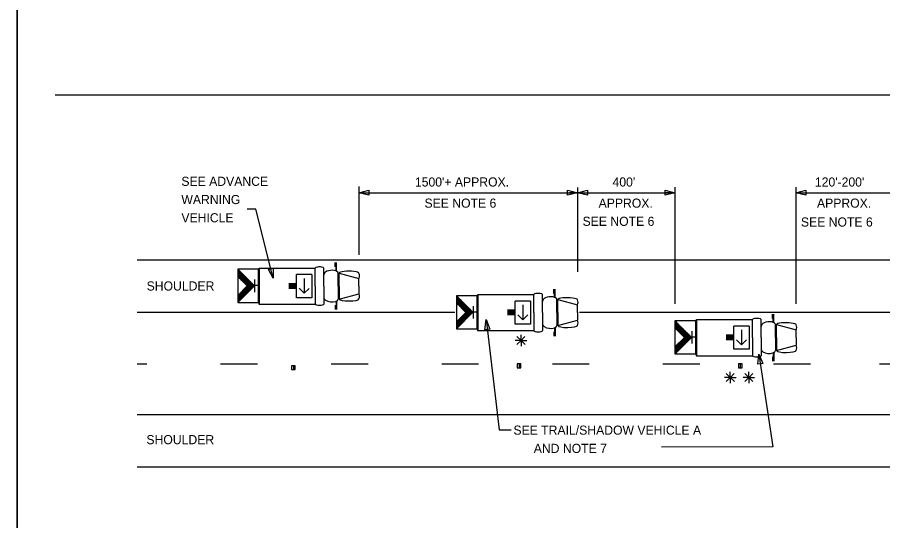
# Model space of a CAD drawing. Extents: x 1374027 to 1374537, y 380415 to 381405.
# Drawn here: x 1374027.1 to 1374084, y 381338.9 to 381372.1 of the extents above; entities that cross this region are included whole.
import ezdxf

# ---------------------------------------------------------------- set-up
doc = ezdxf.new("R2010")
doc.units = 0
for name, color, linetype in [('DSN_DRFT_Junk-No-Plot', 7, 'Continuous'), ('Level 1', 7, 'Continuous'), ('Working Level 1', 7, 'Continuous')]:
    doc.layers.add(name, color=color, linetype=linetype)

msp = doc.modelspace()

# ---------------------------------------------------------------- linework, layer by layer
at = {"layer": 'DSN_DRFT_Junk-No-Plot'}
for points in [[(1374027.083, 381405.174), (1374197.083, 381405.174), (1374197.083, 381295.174), (1374027.083, 381295.174)], [(1374027.083, 381405.174), (1374027.083, 381295.174), (1374197.083, 381295.174), (1374197.083, 381405.174)]]:
    msp.add_lwpolyline(points, close=True, dxfattribs=at)
at = {"layer": 'Level 1'}
msp.add_lwpolyline([(1374075.872, 381349.898), (1374076.792, 381343.794), (1374069.464, 381343.766)], dxfattribs=at)
at = {"layer": 'Working Level 1'}
for p, q in [((1374029.583, 381366.948), (1374114.982, 381366.948)), ((1374049.557, 381360.921), (1374049.557, 381356.423)), ((1374063.944, 381360.862), (1374063.944, 381355.317)), ((1374070.358, 381360.886), (1374070.358, 381353.197)), ((1374078.312, 381360.886), (1374078.312, 381353.197)), ((1374049.557, 381360.515), (1374050.113, 381360.515)), ((1374049.557, 381360.515), (1374063.944, 381360.515)), ((1374063.944, 381360.515), (1374063.415, 381360.515)), ((1374063.944, 381360.515), (1374064.562, 381360.515)), ((1374063.944, 381360.515), (1374070.358, 381360.515)), ((1374070.285, 381360.515), (1374069.756, 381360.515)), ((1374078.312, 381360.515), (1374078.93, 381360.515)), ((1374078.312, 381360.515), (1374084.726, 381360.515)), ((1374034.976, 381356.094), (1374114.982, 381356.094)), ((1374048.007, 381355.628), (1374048.007, 381355.919)), ((1374048.054, 381355.349), (1374048.054, 381355.919)), ((1374048.093, 381355.349), (1374048.093, 381355.919)), ((1374041.585, 381355.48), (1374042.68, 381354.385)), ((1374042.995, 381355.53), (1374042.995, 381353.153)), ((1374043.005, 381355.558), (1374043.005, 381353.181)), ((1374043.005, 381353.18), (1374043.005, 381355.557)), ((1374043.005, 381355.557), (1374046.684, 381355.557)), ((1374046.468, 381355.13), (1374045.462, 381355.13)), ((1374045.462, 381353.608), (1374045.462, 381355.13)), ((1374046.468, 381355.13), (1374046.468, 381353.608)), ((1374046.684, 381354.369), (1374046.684, 381355.557)), ((1374047.248, 381354.369), (1374047.248, 381355.557)), ((1374048.192, 381354.369), (1374048.192, 381355.225)), ((1374048.271, 381355.225), (1374049.557, 381354.873)), ((1374048.271, 381354.369), (1374048.271, 381355.225)), ((1374041.585, 381355.005), (1374042.213, 381354.378)), ((1374042.717, 381353.973), (1374042.717, 381354.797)), ((1374045.462, 381354.521), (1374044.95, 381354.521)), ((1374045.965, 381354.871), (1374045.965, 381353.898)), ((1374049.557, 381354.369), (1374049.557, 381354.873)), ((1374041.585, 381353.752), (1374042.213, 381354.378)), ((1374041.59, 381353.295), (1374042.68, 381354.385)), ((1374042.946, 381354.405), (1374042.711, 381354.405)), ((1374045.462, 381354.445), (1374044.95, 381354.445)), ((1374045.462, 381354.369), (1374044.95, 381354.369)), ((1374045.462, 381354.293), (1374044.95, 381354.293)), ((1374045.462, 381354.217), (1374044.95, 381354.217)), ((1374045.965, 381353.898), (1374045.634, 381354.229)), ((1374045.965, 381353.898), (1374046.288, 381354.221)), ((1374046.684, 381354.369), (1374046.684, 381353.181)), ((1374047.248, 381354.369), (1374047.248, 381353.181)), ((1374048.192, 381354.369), (1374048.192, 381353.513)), ((1374048.271, 381354.369), (1374048.271, 381353.513)), ((1374049.557, 381354.369), (1374049.557, 381353.865)), ((1374062.394, 381353.887), (1374062.394, 381354.178)), ((1374062.44, 381353.607), (1374062.44, 381354.178)), ((1374062.479, 381353.607), (1374062.479, 381354.178)), ((1374046.468, 381353.608), (1374045.462, 381353.608)), ((1374048.054, 381353.39), (1374048.054, 381352.819)), ((1374048.093, 381353.39), (1374048.093, 381352.819)), ((1374048.271, 381353.513), (1374049.557, 381353.865)), ((1374055.971, 381353.739), (1374057.067, 381352.644)), ((1374057.382, 381353.789), (1374057.382, 381351.412)), ((1374057.391, 381353.817), (1374057.391, 381351.44)), ((1374057.391, 381351.439), (1374057.391, 381353.816)), ((1374057.391, 381353.816), (1374061.071, 381353.816)), ((1374060.854, 381353.388), (1374059.849, 381353.388)), ((1374059.849, 381351.867), (1374059.849, 381353.388)), ((1374060.854, 381353.388), (1374060.854, 381351.867)), ((1374061.071, 381352.628), (1374061.071, 381353.816)), ((1374061.634, 381352.628), (1374061.634, 381353.816)), ((1374062.579, 381352.628), (1374062.579, 381353.484)), ((1374062.657, 381353.484), (1374063.943, 381353.132)), ((1374062.657, 381352.628), (1374062.657, 381353.484)), ((1374043.005, 381353.181), (1374046.684, 381353.181)), ((1374048.007, 381353.109), (1374048.007, 381352.819)), ((1374055.971, 381353.263), (1374056.599, 381352.637)), ((1374057.104, 381352.232), (1374057.104, 381353.056)), ((1374059.849, 381352.779), (1374059.336, 381352.779)), ((1374060.352, 381353.13), (1374060.352, 381352.157)), ((1374063.943, 381352.628), (1374063.943, 381353.132)), ((1374034.976, 381352.646), (1374049.603, 381352.646)), ((1374049.581, 381352.646), (1374055.876, 381352.646)), ((1374055.971, 381352.011), (1374056.599, 381352.637)), ((1374055.977, 381351.554), (1374057.067, 381352.644)), ((1374057.333, 381352.664), (1374057.097, 381352.664)), ((1374059.849, 381352.703), (1374059.336, 381352.703)), ((1374059.849, 381352.627), (1374059.336, 381352.627)), ((1374059.849, 381352.551), (1374059.336, 381352.551)), ((1374059.849, 381352.475), (1374059.336, 381352.475)), ((1374060.352, 381352.157), (1374060.021, 381352.488)), ((1374060.352, 381352.157), (1374060.675, 381352.48)), ((1374061.071, 381352.628), (1374061.071, 381351.44)), ((1374061.634, 381352.628), (1374061.634, 381351.44)), ((1374062.579, 381352.628), (1374062.579, 381351.772)), ((1374062.657, 381352.628), (1374062.657, 381351.772)), ((1374063.943, 381352.628), (1374063.943, 381352.124)), ((1374064.074, 381352.646), (1374114.982, 381352.646)), ((1374076.781, 381352.239), (1374076.781, 381352.53)), ((1374076.827, 381351.96), (1374076.827, 381352.53)), ((1374076.866, 381351.96), (1374076.866, 381352.53)), ((1374060.854, 381351.867), (1374059.849, 381351.867)), ((1374062.44, 381351.648), (1374062.44, 381351.078)), ((1374062.479, 381351.648), (1374062.479, 381351.078)), ((1374062.657, 381351.772), (1374063.943, 381352.124)), ((1374070.358, 381352.091), (1374071.453, 381350.996)), ((1374070.358, 381351.616), (1374070.986, 381350.989)), ((1374071.768, 381352.141), (1374071.768, 381349.764)), ((1374071.778, 381352.169), (1374071.778, 381349.792)), ((1374071.778, 381349.791), (1374071.778, 381352.168)), ((1374071.778, 381352.168), (1374075.457, 381352.168)), ((1374075.241, 381351.741), (1374074.236, 381351.741)), ((1374074.236, 381350.219), (1374074.236, 381351.741)), ((1374075.241, 381351.741), (1374075.241, 381350.219)), ((1374075.457, 381350.98), (1374075.457, 381352.168)), ((1374076.021, 381350.98), (1374076.021, 381352.168)), ((1374076.965, 381350.98), (1374076.965, 381351.836)), ((1374077.044, 381351.836), (1374078.33, 381351.484)), ((1374077.044, 381350.98), (1374077.044, 381351.836)), ((1374057.391, 381351.44), (1374061.071, 381351.44)), ((1374060.227, 381350.784), (1374059.961, 381351.05)), ((1374060.22, 381350.779), (1374060.487, 381351.045)), ((1374060.227, 381350.784), (1374060.227, 381351.161)), ((1374062.394, 381351.368), (1374062.394, 381351.078)), ((1374071.49, 381350.584), (1374071.49, 381351.408)), ((1374074.236, 381351.131), (1374073.723, 381351.131)), ((1374074.236, 381351.056), (1374073.723, 381351.056)), ((1374074.738, 381351.482), (1374074.738, 381350.509)), ((1374078.33, 381350.98), (1374078.33, 381351.484)), ((1374060.227, 381350.784), (1374059.85, 381350.784)), ((1374060.227, 381350.784), (1374059.961, 381350.518)), ((1374060.227, 381350.784), (1374060.493, 381350.518)), ((1374060.227, 381350.784), (1374060.227, 381350.408)), ((1374060.227, 381350.784), (1374060.603, 381350.784)), ((1374070.358, 381350.363), (1374070.986, 381350.989)), ((1374070.364, 381349.906), (1374071.453, 381350.996)), ((1374071.719, 381351.016), (1374071.484, 381351.016)), ((1374074.236, 381350.98), (1374073.723, 381350.98)), ((1374074.236, 381350.904), (1374073.723, 381350.904)), ((1374074.236, 381350.828), (1374073.723, 381350.828)), ((1374074.738, 381350.509), (1374074.408, 381350.84)), ((1374074.738, 381350.509), (1374075.061, 381350.832)), ((1374075.457, 381350.98), (1374075.457, 381349.792)), ((1374076.021, 381350.98), (1374076.021, 381349.792)), ((1374076.965, 381350.98), (1374076.965, 381350.124)), ((1374077.044, 381350.98), (1374077.044, 381350.124)), ((1374077.044, 381350.124), (1374078.33, 381350.476)), ((1374078.33, 381350.98), (1374078.33, 381350.476)), ((1374075.241, 381350.219), (1374074.236, 381350.219)), ((1374076.827, 381350.001), (1374076.827, 381349.43)), ((1374076.866, 381350.001), (1374076.866, 381349.43)), ((1374071.778, 381349.792), (1374075.457, 381349.792)), ((1374076.781, 381349.72), (1374076.781, 381349.43)), ((1374045.371, 381349.123), (1374045.128, 381349.123)), ((1374045.128, 381349.123), (1374045.128, 381348.88)), ((1374045.128, 381348.88), (1374045.371, 381348.88)), ((1374045.25, 381349.123), (1374045.249, 381348.88)), ((1374045.371, 381348.88), (1374045.371, 381349.123)), ((1374060.225, 381349.244), (1374059.982, 381349.244)), ((1374059.982, 381349.244), (1374059.982, 381349.001)), ((1374059.982, 381349.001), (1374060.225, 381349.001)), ((1374060.104, 381349.244), (1374060.104, 381349.001)), ((1374060.225, 381349.001), (1374060.225, 381349.244)), ((1374074.53, 381349.244), (1374074.529, 381349.001)), ((1374074.529, 381349.001), (1374074.772, 381349.001)), ((1374074.772, 381349.244), (1374074.53, 381349.244)), ((1374074.652, 381349.244), (1374074.651, 381349.001)), ((1374074.772, 381349.001), (1374074.772, 381349.244)), ((1374073.999, 381348.349), (1374073.622, 381348.349)), ((1374073.999, 381348.349), (1374073.733, 381348.615)), ((1374073.999, 381348.349), (1374073.733, 381348.083)), ((1374073.992, 381348.344), (1374074.259, 381348.61)), ((1374073.999, 381348.349), (1374073.999, 381348.725)), ((1374073.999, 381348.349), (1374074.265, 381348.083)), ((1374073.999, 381348.349), (1374073.999, 381347.973)), ((1374073.999, 381348.349), (1374074.375, 381348.349)), ((1374075.216, 381348.349), (1374074.839, 381348.349)), ((1374075.216, 381348.349), (1374074.95, 381348.615)), ((1374075.216, 381348.349), (1374074.95, 381348.083)), ((1374075.209, 381348.344), (1374075.476, 381348.61)), ((1374075.216, 381348.349), (1374075.216, 381348.725)), ((1374075.216, 381348.349), (1374075.482, 381348.083)), ((1374075.216, 381348.349), (1374075.216, 381347.973)), ((1374075.216, 381348.349), (1374075.592, 381348.349)), ((1374034.976, 381345.924), (1374099.811, 381345.924)), ((1374034.976, 381342.476), (1374096.124, 381342.476))]:
    msp.add_line(p, q, dxfattribs=at)
for points in [[(1374050.206, 381360.353), (1374049.556, 381360.515), (1374050.206, 381360.678)], [(1374063.294, 381360.678), (1374063.944, 381360.515), (1374063.294, 381360.353)], [(1374064.594, 381360.353), (1374063.944, 381360.515), (1374064.594, 381360.678)], [(1374069.708, 381360.678), (1374070.358, 381360.515), (1374069.708, 381360.353)], [(1374078.962, 381360.353), (1374078.312, 381360.515), (1374078.962, 381360.678)], [(1374041.585, 381355.48), (1374041.585, 381353.295), (1374042.95, 381353.295), (1374042.95, 381355.48)], [(1374043.924, 381355.552), (1374043.927, 381354.882), (1374043.609, 381355.472)], [(1374055.971, 381353.739), (1374055.971, 381351.553), (1374057.337, 381351.553), (1374057.337, 381353.739)], [(1374057.847, 381351.498), (1374057.931, 381352.162), (1374058.169, 381351.536)], [(1374070.358, 381352.091), (1374070.358, 381349.906), (1374071.723, 381349.906), (1374071.723, 381352.091)], [(1374075.808, 381349.231), (1374075.872, 381349.898), (1374076.13, 381349.28)]]:
    msp.add_lwpolyline(points, close=True, dxfattribs=at)
for points in [[(1374043.927, 381354.882), (1374042.773, 381359.426), (1374042.197, 381359.426)], [(1374041.585, 381355.428), (1374042.163, 381354.427)], [(1374041.585, 381355.343), (1374042.048, 381354.539)], [(1374041.585, 381355.256), (1374041.934, 381354.651)], [(1374041.585, 381355.17), (1374041.819, 381354.764)], [(1374041.585, 381355.084), (1374041.705, 381354.876)], [(1374041.634, 381355.432), (1374042.398, 381354.105)], [(1374041.75, 381355.314), (1374042.43, 381354.136)], [(1374041.868, 381355.197), (1374042.462, 381354.168)], [(1374041.985, 381355.079), (1374042.494, 381354.199)], [(1374041.585, 381354.998), (1374041.59, 381354.988)], [(1374042.103, 381354.962), (1374042.525, 381354.231)], [(1374042.22, 381354.844), (1374042.558, 381354.26)], [(1374042.338, 381354.727), (1374042.59, 381354.29)], [(1374042.456, 381354.611), (1374042.619, 381354.326)], [(1374042.564, 381354.503), (1374042.648, 381354.357)], [(1374041.725, 381353.893), (1374041.893, 381353.602)], [(1374041.757, 381353.924), (1374041.925, 381353.633)], [(1374041.788, 381353.956), (1374041.956, 381353.664)], [(1374041.82, 381353.987), (1374041.988, 381353.696)], [(1374041.852, 381354.019), (1374042.02, 381353.727)], [(1374041.883, 381354.051), (1374042.052, 381353.759)], [(1374041.915, 381354.082), (1374042.083, 381353.79)], [(1374041.946, 381354.113), (1374042.114, 381353.822)], [(1374041.978, 381354.145), (1374042.147, 381353.853)], [(1374042.009, 381354.177), (1374042.177, 381353.885)], [(1374042.041, 381354.207), (1374042.209, 381353.916)], [(1374042.073, 381354.24), (1374042.241, 381353.948)], [(1374042.104, 381354.271), (1374042.273, 381353.98)], [(1374042.136, 381354.302), (1374042.304, 381354.01)], [(1374042.167, 381354.334), (1374042.336, 381354.042)], [(1374042.199, 381354.366), (1374042.368, 381354.074)], [(1374041.585, 381353.706), (1374041.735, 381353.444)], [(1374041.585, 381353.619), (1374041.704, 381353.413)], [(1374041.585, 381353.534), (1374041.672, 381353.382)], [(1374041.585, 381353.447), (1374041.641, 381353.35)], [(1374041.585, 381353.361), (1374041.609, 381353.32)], [(1374041.599, 381353.767), (1374041.767, 381353.477)], [(1374041.631, 381353.799), (1374041.799, 381353.507)], [(1374041.662, 381353.83), (1374041.83, 381353.539)], [(1374041.694, 381353.862), (1374041.862, 381353.57)], [(1374055.971, 381353.687), (1374056.549, 381352.686)], [(1374055.971, 381353.602), (1374056.435, 381352.798)], [(1374055.971, 381353.515), (1374056.321, 381352.91)], [(1374055.971, 381353.429), (1374056.206, 381353.023)], [(1374055.971, 381353.343), (1374056.092, 381353.135)], [(1374056.02, 381353.691), (1374056.785, 381352.364)], [(1374056.137, 381353.573), (1374056.817, 381352.395)], [(1374056.254, 381353.456), (1374056.849, 381352.427)], [(1374056.372, 381353.338), (1374056.88, 381352.458)], [(1374055.971, 381353.257), (1374055.977, 381353.247)], [(1374056.489, 381353.221), (1374056.911, 381352.49)], [(1374056.607, 381353.103), (1374056.944, 381352.519)], [(1374056.724, 381352.986), (1374056.977, 381352.549)], [(1374056.842, 381352.869), (1374057.006, 381352.585)], [(1374056.951, 381352.762), (1374057.035, 381352.616)], [(1374056.144, 381352.183), (1374056.311, 381351.892)], [(1374056.175, 381352.214), (1374056.343, 381351.923)], [(1374056.207, 381352.246), (1374056.375, 381351.955)], [(1374056.239, 381352.278), (1374056.406, 381351.986)], [(1374056.27, 381352.309), (1374056.438, 381352.018)], [(1374056.301, 381352.341), (1374056.469, 381352.049)], [(1374056.332, 381352.372), (1374056.501, 381352.081)], [(1374056.365, 381352.404), (1374056.533, 381352.111)], [(1374056.396, 381352.435), (1374056.564, 381352.144)], [(1374056.427, 381352.466), (1374056.596, 381352.175)], [(1374056.459, 381352.499), (1374056.628, 381352.206)], [(1374056.491, 381352.53), (1374056.659, 381352.238)], [(1374056.522, 381352.561), (1374056.69, 381352.269)], [(1374056.553, 381352.593), (1374056.723, 381352.301)], [(1374056.586, 381352.624), (1374056.754, 381352.332)], [(1374055.971, 381351.965), (1374056.122, 381351.703)], [(1374055.971, 381351.878), (1374056.09, 381351.672)], [(1374055.971, 381351.792), (1374056.059, 381351.641)], [(1374055.971, 381351.706), (1374056.028, 381351.609)], [(1374055.971, 381351.62), (1374055.995, 381351.578)], [(1374055.986, 381352.026), (1374056.153, 381351.736)], [(1374056.018, 381352.058), (1374056.185, 381351.766)], [(1374056.049, 381352.088), (1374056.216, 381351.798)], [(1374056.081, 381352.121), (1374056.248, 381351.829)], [(1374056.112, 381352.152), (1374056.28, 381351.861)], [(1374057.931, 381352.162), (1374058.794, 381344.903), (1374059.584, 381344.903)], [(1374070.358, 381352.039), (1374070.936, 381351.038)], [(1374070.358, 381351.954), (1374070.821, 381351.15)], [(1374070.358, 381351.867), (1374070.707, 381351.262)], [(1374070.358, 381351.781), (1374070.592, 381351.375)], [(1374070.358, 381351.695), (1374070.478, 381351.487)], [(1374070.358, 381351.609), (1374070.364, 381351.599)], [(1374070.407, 381352.043), (1374071.172, 381350.716)], [(1374070.523, 381351.925), (1374071.203, 381350.747)], [(1374070.641, 381351.808), (1374071.235, 381350.779)], [(1374070.759, 381351.69), (1374071.267, 381350.81)], [(1374070.876, 381351.573), (1374071.298, 381350.842)], [(1374070.993, 381351.455), (1374071.331, 381350.871)], [(1374071.111, 381351.338), (1374071.363, 381350.901)], [(1374071.229, 381351.222), (1374071.392, 381350.937)], [(1374071.337, 381351.114), (1374071.422, 381350.968)], [(1374070.467, 381350.473), (1374070.635, 381350.181)], [(1374070.498, 381350.504), (1374070.666, 381350.213)], [(1374070.53, 381350.535), (1374070.698, 381350.244)], [(1374070.562, 381350.567), (1374070.73, 381350.275)], [(1374070.593, 381350.598), (1374070.761, 381350.307)], [(1374070.625, 381350.63), (1374070.793, 381350.338)], [(1374070.657, 381350.662), (1374070.825, 381350.37)], [(1374070.688, 381350.693), (1374070.856, 381350.401)], [(1374070.719, 381350.724), (1374070.887, 381350.433)], [(1374070.751, 381350.756), (1374070.92, 381350.464)], [(1374070.783, 381350.788), (1374070.951, 381350.496)], [(1374070.814, 381350.818), (1374070.982, 381350.527)], [(1374070.846, 381350.851), (1374071.014, 381350.559)], [(1374070.877, 381350.882), (1374071.046, 381350.591)], [(1374070.909, 381350.913), (1374071.077, 381350.621)], [(1374070.94, 381350.945), (1374071.109, 381350.653)], [(1374070.972, 381350.977), (1374071.141, 381350.685)], [(1374070.358, 381350.317), (1374070.509, 381350.055)], [(1374070.358, 381350.23), (1374070.477, 381350.024)], [(1374070.358, 381350.145), (1374070.445, 381349.993)], [(1374070.358, 381350.058), (1374070.414, 381349.961)], [(1374070.358, 381349.972), (1374070.382, 381349.931)], [(1374070.372, 381350.378), (1374070.54, 381350.088)], [(1374070.404, 381350.41), (1374070.572, 381350.118)], [(1374070.436, 381350.441), (1374070.603, 381350.15)], [(1374034.976, 381349.247), (1374035.613, 381349.247)], [(1374040.463, 381349.247), (1374042.889, 381349.247)], [(1374047.739, 381349.247), (1374050.164, 381349.247)], [(1374055.014, 381349.247), (1374057.439, 381349.247)], [(1374062.289, 381349.247), (1374064.715, 381349.247)], [(1374069.565, 381349.247), (1374071.99, 381349.247)], [(1374076.84, 381349.247), (1374079.266, 381349.247)], [(1374083.815, 381349.247), (1374086.241, 381349.247)]]:
    msp.add_lwpolyline(points, dxfattribs=at)
for centre in [(1374049.242, 381355.042), (1374049.242, 381353.697), (1374063.629, 381353.3), (1374063.629, 381351.955), (1374078.015, 381351.653), (1374078.015, 381350.307)]:
    msp.add_arc(centre, 0.357, 331.8801, 28.1199, dxfattribs=at)
for centre, major_axis, ratio, start_param, end_param in [((1374046.966, 381355.557), (0.282, 0), 0.269913, 0, 3.141593), ((1374047.72, 381355.167), (0.472, 0.058), 0.503092, 0, 3.141593), ((1374048.914, 381355.218), (0.643, -0.007), 0.2034, 0, 3.141593), ((1374061.352, 381353.816), (0.282, 0), 0.269913, 0, 3.141593), ((1374047.72, 381353.571), (0.472, -0.058), 0.503092, 3.141593, 6.283185), ((1374048.914, 381353.52), (0.643, 0.007), 0.2034, 3.141593, 6.283185), ((1374062.106, 381353.425), (0.472, 0.058), 0.503092, 0, 3.141593), ((1374063.3, 381353.476), (0.643, -0.007), 0.2034, 0, 3.141593), ((1374046.966, 381353.181), (0.282, 0), 0.269913, 3.141593, 6.283185), ((1374075.739, 381352.168), (0.282, 0), 0.269913, 0, 3.141593), ((1374062.106, 381351.83), (0.472, -0.058), 0.503092, 3.141593, 6.283185), ((1374063.3, 381351.779), (0.643, 0.007), 0.2034, 3.141593, 6.283185), ((1374076.493, 381351.778), (0.472, 0.058), 0.503092, 0, 3.141593), ((1374077.687, 381351.829), (0.643, -0.007), 0.2034, 0, 3.141593), ((1374061.352, 381351.44), (0.282, 0), 0.269913, 3.141593, 6.283185), ((1374076.493, 381350.182), (0.472, -0.058), 0.503092, 3.141593, 6.283185), ((1374077.687, 381350.131), (0.643, 0.007), 0.2034, 3.141593, 6.283185), ((1374075.739, 381349.792), (0.282, 0), 0.269913, 3.141593, 6.283185)]:
    msp.add_ellipse(centre, major_axis=major_axis, ratio=ratio, start_param=start_param, end_param=end_param, dxfattribs=at)

# ---------------------------------------------------------------- texts
for s, p in [('SEE ADVANCE ', (1374037.879, 381360.965)), ("1500'+ APPROX.", (1374053.245, 381360.919)), ("400'", (1374066.248, 381360.919)), ("120'-200'", (1374079.563, 381360.919)), ('WARNING ', (1374037.879, 381359.765)), ('SEE NOTE 6', (1374053.875, 381359.528)), ('APPROX.', (1374065.332, 381359.528)), ('APPROX.', (1374079.7, 381359.528)), ('VEHICLE', (1374037.879, 381358.565)), ('SEE NOTE 6', (1374064.276, 381358.334)), ('SEE NOTE 6', (1374078.644, 381358.286)), ('SEE TRAIL/SHADOW VEHICLE A ', (1374059.727, 381344.592)), ('      AND NOTE 7', (1374059.727, 381343.392))]:
    msp.add_text(s, height=0.6, dxfattribs=at).set_placement(p)
for p in [(1374035.594, 381354.079), (1374035.578, 381343.967)]:
    msp.add_text('SHOULDER', height=0.6, rotation=0, dxfattribs=at).set_placement(p)

doc.saveas('drawing.dxf')
